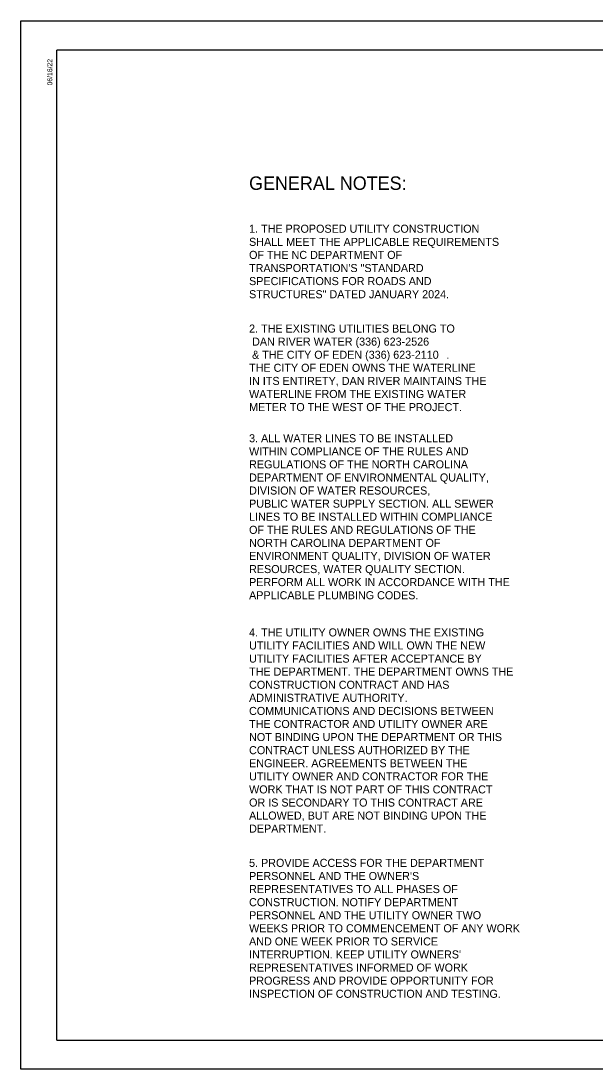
# Model space of a CAD drawing. Extents: x 2787886 to 2789612, y 1113277 to 1114394.
# Drawn here: x 2787886 to 2788498, y 1113277 to 1114394 of the extents above; entities that cross this region are included whole.
import ezdxf

# ---------------------------------------------------------------- set-up
doc = ezdxf.new("R2010")
doc.units = 0
doc.layers.add('Sheet_Plan_And_Profile_CELL', color=7, linetype='Continuous')
doc.layers.add('Sheet_Plot_Border_Outside_CELL', color=7, linetype='Continuous')

msp = doc.modelspace()

# ---------------------------------------------------------------- linework, layer by layer
at = {"layer": 'Sheet_Plan_And_Profile_CELL'}
for p, q in [((2789573.7, 1114363.2), (2787923.7, 1114363.2)), ((2787923.7, 1113308.2), (2787923.7, 1114363.2)), ((2787923.7, 1113308.2), (2789573.7, 1113308.2))]:
    msp.add_line(p, q, dxfattribs=at)
at = {"layer": 'Sheet_Plot_Border_Outside_CELL'}
msp.add_lwpolyline([(2787885.6, 1114394.2), (2789611.8, 1114394.2), (2789611.8, 1113277.3), (2787885.6, 1113277.3)], close=True, dxfattribs=at)

# ---------------------------------------------------------------- texts
at = {"layer": 'Sheet_Plan_And_Profile_CELL'}
msp.add_text('06/16/22', height=5.25, rotation=90, dxfattribs=at).set_placement((2787919, 1114325.5))
for s, height, p in [('GENERAL NOTES:', 14.3, (2788128.8, 1114214.2)), ('1. THE PROPOSED UTILITY CONSTRUCTION ', 8.58, (2788128.8, 1114168.5)), ('SHALL MEET THE APPLICABLE REQUIREMENTS ', 8.58, (2788128.8, 1114154.5)), ('OF THE NC DEPARTMENT OF ', 8.58, (2788128.8, 1114140.6)), ('TRANSPORTATION\'S "STANDARD ', 8.58, (2788128.8, 1114126.6)), ('SPECIFICATIONS FOR ROADS AND ', 8.58, (2788128.8, 1114112.7)), ('STRUCTURES" DATED JANUARY 2024.', 8.58, (2788128.8, 1114098.7)), ('2. THE EXISTING UTILITIES BELONG TO ', 8.58, (2788128.8, 1114062.1)), (' DAN RIVER WATER (336) 623-2526', 8.58, (2788128.8, 1114048.2)), (' & THE CITY OF EDEN (336) 623-2110', 8.58, (2788128.8, 1114034.2)), ('. ', 8.58, (2788338.9, 1114034.2)), ('THE CITY OF EDEN OWNS THE WATERLINE', 8.58, (2788128.8, 1114020.3)), ('IN ITS ENTIRETY, DAN RIVER MAINTAINS THE', 8.58, (2788128.8, 1114006.3)), ('WATERLINE FROM THE EXISTING WATER', 8.58, (2788128.8, 1113992.4)), ('METER TO THE WEST OF THE PROJECT.', 8.58, (2788128.8, 1113978.4)), ('3. ALL WATER LINES TO BE INSTALLED ', 8.58, (2788128.8, 1113945.2)), ('WITHIN COMPLIANCE OF THE RULES AND ', 8.58, (2788128.8, 1113931.3)), ('REGULATIONS OF THE NORTH CAROLINA ', 8.58, (2788128.8, 1113917.4)), ('DEPARTMENT OF ENVIRONMENTAL QUALITY, ', 8.58, (2788128.8, 1113903.4)), ('DIVISION OF WATER RESOURCES,', 8.58, (2788128.8, 1113889.5)), ('PUBLIC WATER SUPPLY SECTION. ALL SEWER ', 8.58, (2788128.8, 1113875.5)), ('LINES TO BE INSTALLED WITHIN COMPLIANCE ', 8.58, (2788128.8, 1113861.6)), ('OF THE RULES AND REGULATIONS OF THE ', 8.58, (2788128.8, 1113847.6)), ('NORTH CAROLINA DEPARTMENT OF ', 8.58, (2788128.8, 1113833.7)), ('ENVIRONMENT QUALITY, DIVISION OF WATER ', 8.58, (2788128.8, 1113819.8)), ('RESOURCES, WATER QUALITY SECTION. ', 8.58, (2788128.8, 1113805.8)), ('PERFORM ALL WORK IN ACCORDANCE WITH THE ', 8.58, (2788128.8, 1113791.9)), ('APPLICABLE PLUMBING CODES.', 8.58, (2788128.8, 1113777.9)), ('4. THE UTILITY OWNER OWNS THE EXISTING ', 8.58, (2788128.8, 1113738.3)), ('UTILITY FACILITIES AND WILL OWN THE NEW ', 8.58, (2788128.8, 1113724.4)), ('UTILITY FACILITIES AFTER ACCEPTANCE BY ', 8.58, (2788128.8, 1113710.4)), ('THE DEPARTMENT. THE DEPARTMENT OWNS THE ', 8.58, (2788128.8, 1113696.5)), ('CONSTRUCTION CONTRACT AND HAS ', 8.58, (2788128.8, 1113682.5)), ('ADMINISTRATIVE AUTHORITY. ', 8.58, (2788128.8, 1113668.6)), ('COMMUNICATIONS AND DECISIONS BETWEEN ', 8.58, (2788128.8, 1113654.6)), ('THE CONTRACTOR AND UTILITY OWNER ARE ', 8.58, (2788128.8, 1113640.7)), ('NOT BINDING UPON THE DEPARTMENT OR THIS ', 8.58, (2788128.8, 1113626.8)), ('CONTRACT UNLESS AUTHORIZED BY THE ', 8.58, (2788128.8, 1113612.8)), ('ENGINEER. AGREEMENTS BETWEEN THE ', 8.58, (2788128.8, 1113598.9)), ('UTILITY OWNER AND CONTRACTOR FOR THE ', 8.58, (2788128.8, 1113584.9)), ('WORK THAT IS NOT PART OF THIS CONTRACT ', 8.58, (2788128.8, 1113571)), ('OR IS SECONDARY TO THIS CONTRACT ARE ', 8.58, (2788128.8, 1113557)), ('ALLOWED, BUT ARE NOT BINDING UPON THE ', 8.58, (2788128.8, 1113543.1)), ('DEPARTMENT.', 8.58, (2788128.8, 1113529.2)), ('5. PROVIDE ACCESS FOR THE DEPARTMENT ', 8.58, (2788128.8, 1113492.7)), ("PERSONNEL AND THE OWNER'S ", 8.58, (2788128.8, 1113478.7)), ('REPRESENTATIVES TO ALL PHASES OF ', 8.58, (2788128.8, 1113464.8)), ('CONSTRUCTION. NOTIFY DEPARTMENT ', 8.58, (2788128.8, 1113450.8)), ('PERSONNEL AND THE UTILITY OWNER TWO ', 8.58, (2788128.8, 1113436.9)), ('WEEKS PRIOR TO COMMENCEMENT OF ANY WORK ', 8.58, (2788128.8, 1113423)), ('AND ONE WEEK PRIOR TO SERVICE ', 8.58, (2788128.8, 1113409)), ("INTERRUPTION. KEEP UTILITY OWNERS' ", 8.58, (2788128.8, 1113395.1)), ('REPRESENTATIVES INFORMED OF WORK ', 8.58, (2788128.8, 1113381.1)), ('PROGRESS AND PROVIDE OPPORTUNITY FOR ', 8.58, (2788128.8, 1113367.2)), ('INSPECTION OF CONSTRUCTION AND TESTING.', 8.58, (2788128.8, 1113353.2))]:
    msp.add_text(s, height=height, dxfattribs=at).set_placement(p)

doc.saveas('drawing.dxf')
